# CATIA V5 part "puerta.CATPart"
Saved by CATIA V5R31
Part number: puerta
Bounding box of the stored display mesh (mm): x -81 to 81, y 0 to 3.3, z -66 to 66
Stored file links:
  C:\Users\189361\Desktop\puerta.CATPart
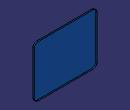
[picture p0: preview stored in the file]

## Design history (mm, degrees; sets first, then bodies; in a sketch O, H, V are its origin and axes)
Body1 (main body)
  Sketch1 on zx-plane, origin (0, 0, 0), H (-1, 0, 0), V (0, 0, 1)
    line L1 (81, 56) -> (81, -56)
    line L2 (71, -66) -> (-71, -66)
    line L3 (-81, -56) -> (-81, 56)
    line L4 (-71, 66) -> (71, 66)
    point P1 (81, 66)
    point P2 (81, -66)
    point P3 (-81, -66)
    arc A1 centre (-71, 56) radius 10 from (-81, 56) to (-71, 66) cw
    arc A2 centre (71, 56) radius 10 from (71, 66) to (81, 56) cw
    arc A3 centre (71, -56) radius 10 from (71, -66) to (81, -56) ccw
    arc A4 centre (-71, -56) radius 10 from (-71, -66) to (-81, -56) cw
    radius A1 = 10
    distance P1 P2 = 132
    radius A2 = 10
    distance P2 P3 = 162
    radius A3 = 10
    radius A4 = 10
    vertical: L1 V, L3 V
    horizontal: L2 H, L4 H
    equidistance: L1 L3 O, L2 L4 O
    tangency: A1 L3, A1 L4, A2 L4, A2 L1, A3 L2, A3 L1, A4 L2, A4 L3
    coincidence: L4 P1, L1 P1, L2 P2, L1 P2, L2 P3, L3 P3
  Pad1: profile Sketch1, direction (0, 1, 0), length 3.3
